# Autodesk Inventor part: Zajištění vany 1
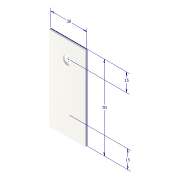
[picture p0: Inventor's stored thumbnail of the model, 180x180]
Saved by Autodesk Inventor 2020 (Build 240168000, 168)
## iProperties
Created: 2025-03
Part Number: Zajištění vany 1
Material: Ocel
Document SubType Name: Modeling
Designer: doma
Density: 7.85 g/cm^3
Appearance: Ocel
Author: doma
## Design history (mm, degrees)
sketch "Náčrt1"
  geometry: L1 (-15, -35)-(15, -35); L2 (15, -35)-(15, 35); L3 (15, 35)-(-15, 35); L4 (-15, 35)-(-15, -35); L5 (-15, -35)-(15, 35); L6 (15, -35)-(-15, 35); 3 further points
  constraints: 12 end point, 2 midpoint, 2 parallel, 1 horizontal, 1 perpendicular
  dimensions: "d3" = 30 distance of L3.end L2.end; "d4" = 70 distance of L2.end L1.end; "d14" = 15 distance from line of L1 point (0, -20); "d15" = 15 distance from line of L3 point (0, 20)
extrude "Vysunutí1" new body sketch "Náčrt1" distance "d5" = 1.6; taper "d6" = 0 deg
hole "Díra1" sketch "Náčrt1" diameter "d7" = 7; stored, may be unused: countersink angle "d11" = 90 deg, drill point angle "d13" = 118 deg; dims "d8" = 6, "d9" = 4, "d10" = 2, "d12" = 8
node "Těleso1"
